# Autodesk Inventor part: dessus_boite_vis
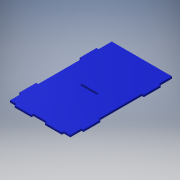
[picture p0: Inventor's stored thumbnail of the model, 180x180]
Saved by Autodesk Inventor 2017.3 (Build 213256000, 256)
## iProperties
Part Number: dessus_boite_vis
Material: Générique
Document SubType Name: Modeling
Designer: ficho
Density: 1 g/cm^3
Appearance: Bleu - Peinture murale - Brillant
Author: ficho
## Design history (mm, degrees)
sketch "Esquisse1"
  geometry: L1 (90.09, 155)-(0, 155); L2 (90, 20)-(93, 20) reference; L3 (90, 44.7)-(93, 44.7) reference; L4 (90, 110.3)-(93, 110.3) reference; L5 (90, 135)-(93, 135) reference; L6 (80.09, 0)-(80.09, 3) reference; L7 (55.39, 0)-(55.39, 3) reference; L8 (34.7, 0)-(34.7, 3) reference; L9 (10, 0)-(10, 3) reference; L10 (-3, 20)-(0, 20) reference; L11 (-3, 44.7)-(0, 44.7) reference; L12 (-3, 110.3)-(0, 110.3) reference; L13 (-3, 135)-(0, 135) reference; L14 (-3, 19.7)-(0, 19.7); L15 (0, 45)-(-3, 45); L16 (-3, 45)-(-3, 19.7); L17 (-3, 110)-(0, 110); L18 (0, 135.3)-(-3, 135.3); L19 (-3, 135.3)-(-3, 110); L20 (90.09, 110)-(93, 110); L21 (93, 110)-(93, 135.3); L22 (93, 135.3)-(90.09, 135.3); L23 (90.09, 19.7)-(93, 19.7); L24 (93, 19.7)-(93, 45); L25 (93, 45)-(90.09, 45); L26 (55.09, 0)-(80.39, 0); L27 (80.39, 0)-(80.39, 3); L28 (55.09, 3)-(55.09, 0); L29 (9.7, 0)-(35, 0); L30 (35, 0)-(35, 3); L31 (9.7, 3)-(9.7, 0); L32 (90.09, 155)-(90.09, 135.3); L33 (90.09, 110)-(90.09, 45); L34 (90.09, 19.7)-(90.09, 3); L35 (90.09, 3)-(80.39, 3); L36 (55.09, 3)-(35, 3); L37 (9.7, 3)-(0, 3); L38 (0, 3)-(0, 19.7); L39 (0, 45)-(0, 110); L40 (0, 135.3)-(0, 155); 3 further points
  constraints: 62 end point, 8 point on line, 7 perpendicular, 6 horizontal, 6 parallel, 2 collinear, 1 vertical, 2 other
  dimensions: "d0" = 0.3 distance between parallel lines of L10 L14; "d1" = 0.3 distance between parallel lines of L15 L11 (= d0); "d2" = 0.3 distance between parallel lines of L12 L17 (= d1); "d3" = 0.3 distance between parallel lines of L18 L13 (= d2); "d4" = 0.3 distance between parallel lines of L5 L22 (derived); "d5" = 0.3 distance between parallel lines of L4 L20 (= d2); "d6" = 0.3 distance between parallel lines of L2 L23 (derived); "d7" = 0.3 distance between parallel lines of L25 L3 (= d1); "d8" = 0.3 distance between parallel lines of L30 L8 (= d1); "d9" = 0.3 distance between parallel lines of L31 L9 (= d8); "d10" = 0.3 distance between parallel lines of L6 L27 (= d8); "d11" = 0.3 distance between parallel lines of L28 L7; "d14" = 96 distance between parallel lines of L16 L24; "d15" = 96 distance between parallel lines of L19 L21 (derived)
extrude "Extrusion1" new body sketch "Esquisse1" distance "d12" = 3; taper "d13" = 0 deg
sketch "Esquisse2"
  geometry: L1 (32.35, 78)-(57.65, 78) reference; L2 (32.35, 75)-(57.65, 75) reference; L3 (57.35, 78)-(32.65, 78); L4 (32.65, 78)-(32.65, 75); L5 (32.65, 75)-(57.35, 75); L6 (57.35, 75)-(57.35, 78); 1 further point
  constraints: 8 end point, 2 parallel, 2 point on line, 1 horizontal, 1 perpendicular
  dimensions: "d16" = 0.3 distance from line of L6 L1.end; "d17" = 0.3 distance from line of L4 L1.start (= d16)
extrude "Extrusion2" cut sketch "Esquisse2" stored distance "d18" = 3; taper "d19" = 0 deg
node "Solide1"
node "Référence1"
node "Référence2"
node "Référence5"
node "Référence6"
node "Référence7"
node "Référence8"
node "Référence9"
node "Référence10"
node "Référence11"
node "Référence12"
node "Référence13"
node "Référence14"
node "Référence15"
node "Référence16"
node "Référence17"
node "Référence18"
